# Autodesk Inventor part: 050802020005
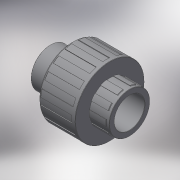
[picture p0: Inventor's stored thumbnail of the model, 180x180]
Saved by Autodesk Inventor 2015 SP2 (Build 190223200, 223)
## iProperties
Created: 2017-10
Part Number: 050802020005
Material: Generic
Description: PLASSON UNION+O RING THR-CEM 20-1/2"
Document SubType Name: Modeling
Designer: KIM
Density: 1 g/cm^3
Appearance: Default
Author: KIM
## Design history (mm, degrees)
derived "050802.ipt"
feature "Solid1::050802.ipt"
tag "TaggingFeature1"
body "Solid1"
other parameters: "d0" = 46, "d4" = 18.631, "d5" = 24, "d6" = 25, "d7" = 25.6, "d8" = 42, "d9" = 16, "d10" = 17, "d11" = 17, "d12" = 19, "d14" = 12.75, "d15" = 12, "d16" = 11.7, "d17" = 1.7, "d19" = 41.16, "d20" = 1.6, "d21" = 1.26, "d25" = 4.2, "d26" = 2.1, "d27" = 17.685, "d28" = 0, "d32" = 4.2, "d33" = 2.1, "d35" = 0, "d39" = 0.2, "d45" = 0.3, "d49" = 360 deg, "d51" = 0.42, "d55" = 360 deg, "E_" = 42, "H_" = 39, "l_" = 16, "lt_" = 17, "Z_" = 11, "G_" = 18.631, "d13" = 13, "d24" = 19.65, "d40" = 0.3, "d44" = 0.42
